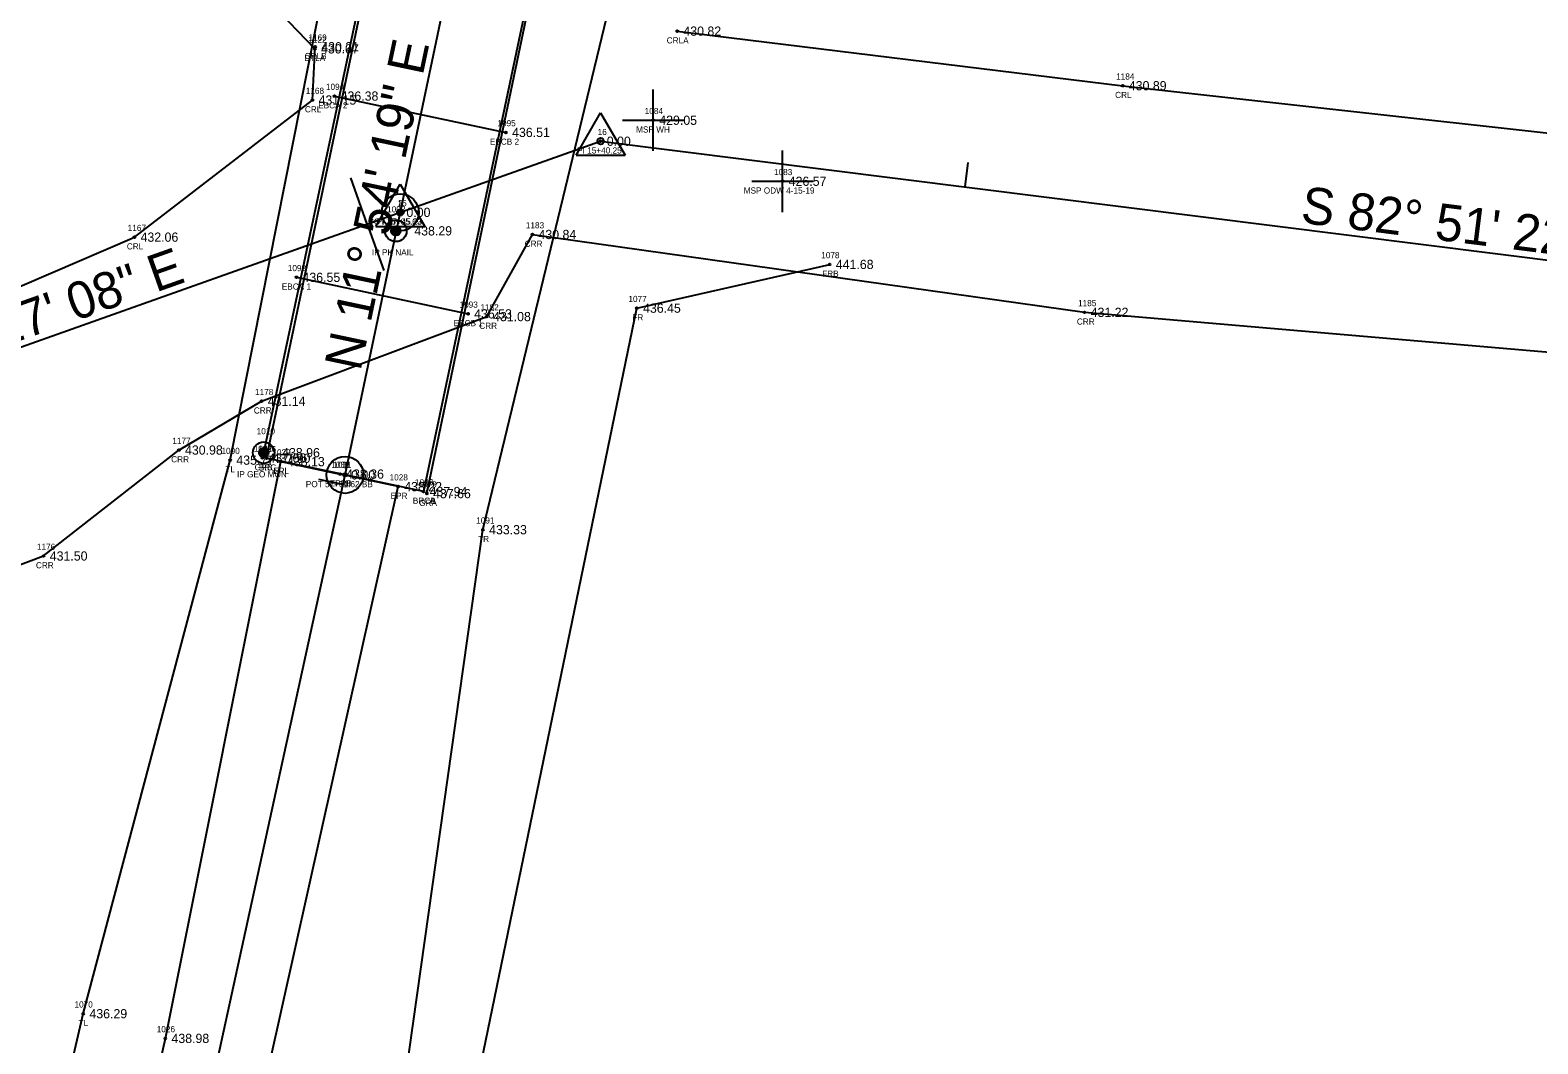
# Model space of a CAD drawing. Extents: x 1754677 to 1756729, y 972996 to 978369.
# Drawn here: x 1756142.4 to 1756387.5, y 976466.6 to 976631.3 of the extents above; entities that cross this region are included whole.
import ezdxf

# ---------------------------------------------------------------- set-up
doc = ezdxf.new("R2010")
doc.units = 0
for name, color, linetype in [('RD_EX_Bridge', 7, 'Continuous'), ('RD_EX_Bridge_txCode', 7, 'Continuous'), ('RD_EX_DV_Prop_txCode', 7, 'Continuous'), ('RD_EX_DV_PropPin', 7, 'Continuous'), ('RD_EX_Fence_Other', 7, 'Continuous'), ('RD_EX_Fence_Other_txCode', 7, 'Continuous'), ('RD_EX_GuardRail', 7, 'Continuous'), ('RD_EX_GuardRail_txCode', 7, 'Continuous'), ('RD_EX_H2O', 7, 'Continuous'), ('RD_EX_H2O_txCode', 7, 'Continuous'), ('RD_EX_Road', 7, 'Continuous'), ('RD_EX_Road_txCode', 7, 'Continuous'), ('RD_EX_TX_Bridge_ELEV', 7, 'Continuous'), ('RD_EX_TX_DV_Prop_ELEV', 7, 'Continuous'), ('RD_EX_TX_Fence_Other_ELEV', 7, 'Continuous'), ('RD_EX_TX_GuardRail_ELEV', 7, 'Continuous'), ('RD_EX_TX_H2O_ELEV', 7, 'Continuous'), ('RD_EX_TX_Misc_ELEV', 7, 'Continuous'), ('RD_EX_TX_Road_ELEV', 7, 'Continuous'), ('RD_EX_TX_VEG_ELEV', 7, 'Continuous'), ('RD_EX_VEG', 7, 'Continuous'), ('RD_EX_VEG_txCode', 7, 'Continuous'), ('RD_HC_Cl', 7, 'Continuous'), ('RD_HC_Data', 7, 'Continuous'), ('RD_HC_Data_Tic', 7, 'Continuous'), ('RD_HC_Survey_ELEV', 7, 'Continuous'), ('RD_HC_txCode', 7, 'Continuous'), ('RD_SMD_Locator', 7, 'Continuous')]:
    doc.layers.add(name, color=color, linetype=linetype)

msp = doc.modelspace()

# ---------------------------------------------------------------- linework, layer by layer
at = {"layer": 'RD_EX_Bridge'}
for p, q in [((1756191.87, 976620.6), (1756219.75, 976614.69)), ((1756185.67, 976591.14), (1756213.58, 976585.2))]:
    msp.add_line(p, q, dxfattribs=at)
msp.add_lwpolyline([(1756206.34, 976556.33), (1756180.82, 976561.73), (1756199.29, 976649.61), (1756224.9, 976644.09), (1756206.34, 976556.33)], dxfattribs=at)
at = {"layer": 'RD_EX_DV_PropPin'}
for p, q in [((1756201.11, 976598.49), (1756201.11, 976598.88)), ((1756201.15, 976598.39), (1756201.15, 976598.99)), ((1756201.18, 976598.32), (1756201.18, 976599.06)), ((1756201.22, 976598.26), (1756201.22, 976599.11)), ((1756201.25, 976598.21), (1756201.25, 976599.16)), ((1756201.29, 976598.17), (1756201.29, 976599.2)), ((1756201.32, 976598.14), (1756201.32, 976599.24)), ((1756201.36, 976598.11), (1756201.36, 976599.27)), ((1756201.39, 976598.08), (1756201.39, 976599.3)), ((1756201.43, 976598.05), (1756201.43, 976599.32)), ((1756201.46, 976598.03), (1756201.46, 976599.34)), ((1756201.5, 976598.01), (1756201.5, 976599.36)), ((1756201.53, 976598), (1756201.53, 976599.38)), ((1756201.57, 976597.98), (1756201.57, 976599.4)), ((1756201.6, 976597.97), (1756201.6, 976599.41)), ((1756201.64, 976597.96), (1756201.64, 976599.42)), ((1756201.67, 976597.95), (1756201.67, 976599.43)), ((1756201.71, 976597.94), (1756201.71, 976599.44)), ((1756201.74, 976597.93), (1756201.74, 976599.44)), ((1756201.78, 976597.93), (1756201.78, 976599.45)), ((1756201.81, 976597.93), (1756201.81, 976599.45)), ((1756201.85, 976597.93), (1756201.85, 976599.45)), ((1756201.88, 976597.93), (1756201.88, 976599.45)), ((1756201.92, 976597.93), (1756201.92, 976599.45)), ((1756201.95, 976597.93), (1756201.95, 976599.44)), ((1756201.99, 976597.94), (1756201.99, 976599.44)), ((1756202.02, 976597.95), (1756202.02, 976599.43)), ((1756202.06, 976597.96), (1756202.06, 976599.42)), ((1756202.09, 976597.97), (1756202.09, 976599.41)), ((1756202.13, 976597.98), (1756202.13, 976599.4)), ((1756202.16, 976598), (1756202.16, 976599.38)), ((1756202.2, 976598.01), (1756202.2, 976599.36)), ((1756202.23, 976598.03), (1756202.23, 976599.34)), ((1756202.27, 976598.05), (1756202.27, 976599.32)), ((1756202.3, 976598.08), (1756202.3, 976599.3)), ((1756202.34, 976598.11), (1756202.34, 976599.27)), ((1756202.37, 976598.14), (1756202.37, 976599.24)), ((1756202.41, 976598.17), (1756202.41, 976599.2)), ((1756202.44, 976598.21), (1756202.44, 976599.16)), ((1756202.48, 976598.26), (1756202.48, 976599.11)), ((1756202.51, 976598.32), (1756202.51, 976599.06)), ((1756202.55, 976598.39), (1756202.55, 976598.99)), ((1756202.58, 976598.49), (1756202.58, 976598.88)), ((1756179.63, 976562.44), (1756179.63, 976562.84)), ((1756179.66, 976562.34), (1756179.66, 976562.94)), ((1756179.7, 976562.27), (1756179.7, 976563.01)), ((1756179.73, 976562.21), (1756179.73, 976563.07)), ((1756179.77, 976562.17), (1756179.77, 976563.11)), ((1756179.8, 976562.12), (1756179.8, 976563.15)), ((1756179.84, 976562.09), (1756179.84, 976563.19)), ((1756179.87, 976562.06), (1756179.87, 976563.22)), ((1756179.91, 976562.03), (1756179.91, 976563.25)), ((1756179.94, 976562.01), (1756179.94, 976563.27)), ((1756179.98, 976561.98), (1756179.98, 976563.3)), ((1756180.01, 976561.96), (1756180.01, 976563.32)), ((1756180.05, 976561.95), (1756180.05, 976563.33)), ((1756180.08, 976561.93), (1756180.08, 976563.35)), ((1756180.12, 976561.92), (1756180.12, 976563.36)), ((1756180.15, 976561.91), (1756180.15, 976563.37)), ((1756180.19, 976561.9), (1756180.19, 976563.38)), ((1756180.22, 976561.89), (1756180.22, 976563.39)), ((1756180.26, 976561.89), (1756180.26, 976563.39)), ((1756180.29, 976561.88), (1756180.29, 976563.4)), ((1756180.33, 976561.88), (1756180.33, 976563.4)), ((1756180.36, 976561.88), (1756180.36, 976563.4)), ((1756180.4, 976561.88), (1756180.4, 976563.4)), ((1756180.43, 976561.88), (1756180.43, 976563.4)), ((1756180.47, 976561.89), (1756180.47, 976563.39)), ((1756180.5, 976561.89), (1756180.5, 976563.39)), ((1756180.54, 976561.9), (1756180.54, 976563.38)), ((1756180.57, 976561.91), (1756180.57, 976563.37)), ((1756180.61, 976561.92), (1756180.61, 976563.36)), ((1756180.64, 976561.93), (1756180.64, 976563.35)), ((1756180.68, 976561.95), (1756180.68, 976563.33)), ((1756180.71, 976561.96), (1756180.71, 976563.32)), ((1756180.75, 976561.98), (1756180.75, 976563.3)), ((1756180.78, 976562.01), (1756180.78, 976563.27)), ((1756180.82, 976562.03), (1756180.82, 976563.25)), ((1756180.85, 976562.06), (1756180.85, 976563.22)), ((1756180.89, 976562.09), (1756180.89, 976563.19)), ((1756180.92, 976562.12), (1756180.92, 976563.15)), ((1756180.96, 976562.17), (1756180.96, 976563.11)), ((1756180.99, 976562.21), (1756180.99, 976563.07)), ((1756181.03, 976562.27), (1756181.03, 976563.01)), ((1756181.06, 976562.34), (1756181.06, 976562.94)), ((1756181.1, 976562.44), (1756181.1, 976562.84))]:
    msp.add_line(p, q, dxfattribs=at)
for centre, radius in [((1756201.85, 976598.69), 1.75), ((1756201.85, 976598.69), 0.761), ((1756180.36, 976562.64), 1.75), ((1756180.36, 976562.64), 0.761)]:
    msp.add_circle(centre, radius, dxfattribs=at)
at = {"layer": 'RD_EX_Fence_Other'}
msp.add_lwpolyline([(1756175.64, 976319.57), (1756180.92, 976337.06), (1756180.92, 976337.06), (1756189.99, 976367.43), (1756214.31, 976456.61), (1756241.04, 976586.13), (1756272.38, 976593.24)], dxfattribs=at)
at = {"layer": 'RD_EX_GuardRail'}
for p, q in [((1756198.88, 976649.87), (1756180.14, 976561.78)), ((1756206.9, 976555.99), (1756225.37, 976644.33))]:
    msp.add_line(p, q, dxfattribs=at)
at = {"layer": 'RD_EX_H2O'}
for p, q in [((1756243.68, 976611.67), (1756243.68, 976621.67)), ((1756238.68, 976616.67), (1756248.68, 976616.67)), ((1756264.72, 976601.75), (1756264.72, 976611.75)), ((1756259.72, 976606.75), (1756269.72, 976606.75))]:
    msp.add_line(p, q, dxfattribs=at)
for points in [[(1756188.69, 976628.27), (1756159.54, 976658.6), (1756134.34, 976641.66), (1756096.42, 976639.72), (1756159.17, 976666.78), (1756147.63, 976691.44)], [(1756247.6, 976631.15), (1756320.02, 976622.28), (1756426.93, 976610.4), (1756522.42, 976596.33), (1756612.51, 976536.45), (1756713.08, 976499.13)], [(1755737.32, 976440.59), (1755791.96, 976465.24), (1755883.28, 976455.13), (1755971.27, 976482.19), (1756023.59, 976552.72), (1756109.16, 976576.08), (1756159.34, 976597.67), (1756188.28, 976619.95), (1756188.72, 976628.61)], [(1755755.31, 976405), (1755806.36, 976424.52), (1755883.37, 976426.21), (1755989.26, 976449.51), (1756040.99, 976524.41), (1756109.22, 976532.55), (1756144.58, 976545.85), (1756166.57, 976563.07), (1756180.02, 976571), (1756216.66, 976584.76), (1756224.04, 976598.1), (1756313.82, 976585.45), (1756418.42, 976576.49), (1756511.71, 976558.86), (1756604.42, 976511.73), (1756702.67, 976481.09)]]:
    msp.add_lwpolyline(points, dxfattribs=at)
for centre in [(1756243.68, 976616.67), (1756264.72, 976606.75)]:
    msp.add_circle(centre, 0.15, dxfattribs=at)
at = {"layer": 'RD_EX_Road'}
for points in [[(1756035.19, 975875.88), (1756056.24, 975973.07), (1756076.6, 976069.51), (1756097.1, 976167.18), (1756119.62, 976269.35), (1756142.72, 976371.31), (1756164.37, 976467.45), (1756183.15, 976561.19), (1756192.77, 976559.17)], [(1756056.66, 975870.37), (1756077.66, 975967.46), (1756097.63, 976065.09), (1756118.05, 976161.7), (1756139.04, 976265.41), (1756152.93, 976328.23), (1756161.13, 976367.36), (1756181.28, 976463.3), (1756202.22, 976557.13), (1756192.77, 976559.17)]]:
    msp.add_lwpolyline(points, dxfattribs=at)
at = {"layer": 'RD_EX_VEG'}
for points in [[(1756025.5, 975878.35), (1756043.1, 975975.5), (1756066.95, 976073.5), (1756085.77, 976169.9), (1756104.86, 976272.18), (1756128.74, 976375.38), (1756151.03, 976471.46), (1756174.91, 976561.43), (1756192.74, 976651.33), (1756213.53, 976750.19), (1756228.91, 976849.58), (1756256.36, 976947.04), (1756269.46, 977047.7), (1756289.25, 977149.19), (1756313.02, 977250.02), (1756334.73, 977344.93)], [(1756202.82, 976314.6), (1756169.5, 976324.56), (1756203.44, 976461.03), (1756216.01, 976550.12), (1756241.68, 976656.38), (1756259.33, 976737.2), (1756283.06, 976837.69), (1756302.86, 976939.77), (1756320.41, 977034.15), (1756341.85, 977139.2), (1756364.03, 977240.9), (1756380.52, 977337.93)]]:
    msp.add_lwpolyline(points, dxfattribs=at)
at = {"layer": 'RD_HC_Cl'}
for p, q in [((1756193.58, 976559.03), (1756212.09, 976646.85)), ((1756051.41, 976548.03), (1756235.14, 976613.26)), ((1756235.14, 976613.26), (1756516.31, 976578.02)), ((1756107.58, 976164.44), (1756193.58, 976559.03))]:
    msp.add_line(p, q, dxfattribs=at)
at = {"layer": 'RD_HC_Data'}
for p, q in [((1756231.16, 976610.97), (1756235.14, 976617.85)), ((1756235.14, 976617.85), (1756239.11, 976610.97)), ((1756231.16, 976610.97), (1756239.11, 976610.97)), ((1756198.6, 976599.41), (1756202.57, 976606.29)), ((1756202.57, 976606.29), (1756206.54, 976599.41)), ((1756198.6, 976599.41), (1756206.54, 976599.41))]:
    msp.add_line(p, q, dxfattribs=at)
for centre, radius in [((1756235.14, 976613.26), 0.529), ((1756202.57, 976601.7), 3), ((1756202.57, 976601.7), 0.529), ((1756202.57, 976601.7), 0.282), ((1756193.58, 976559.03), 3), ((1756193.58, 976559.03), 0.282)]:
    msp.add_circle(centre, radius, dxfattribs=at)
at = {"layer": 'RD_HC_Data_Tic'}
for p, q in [((1756294.42, 976605.83), (1756294.92, 976609.8)), ((1756197.21, 976599.8), (1756194.53, 976607.33)), ((1756197.21, 976599.8), (1756199.88, 976592.26)), ((1756193.23, 976557.45), (1756189.32, 976558.3))]:
    msp.add_line(p, q, dxfattribs=at)
at = {"layer": 'RD_SMD_Locator'}
for centre in [(1756247.6, 976631.15), (1756188.69, 976628.27), (1756188.72, 976628.61), (1756320.02, 976622.28), (1756188.28, 976619.95), (1756191.87, 976620.6), (1756219.75, 976614.69), (1756235.14, 976613.26), (1756202.57, 976601.7), (1756202.57, 976601.7), (1756159.34, 976597.67), (1756201.85, 976598.69), (1756224.04, 976598.1), (1756272.38, 976593.24), (1756185.67, 976591.14), (1756213.58, 976585.2), (1756216.66, 976584.76), (1756241.04, 976586.13), (1756313.82, 976585.45), (1756180.02, 976571), (1756166.57, 976563.07), (1756180.36, 976562.64), (1756174.91, 976561.43), (1756180.14, 976561.78), (1756180.82, 976561.73), (1756183.15, 976561.19), (1756192.77, 976559.17), (1756192.77, 976559.17), (1756193.58, 976559.03), (1756202.22, 976557.13), (1756206.34, 976556.33), (1756206.34, 976556.33), (1756206.9, 976555.99), (1756216.01, 976550.12), (1756144.58, 976545.85), (1756151.03, 976471.46), (1756164.37, 976467.45)]:
    msp.add_circle(centre, 0.15, dxfattribs=at)

# ---------------------------------------------------------------- texts
at = {"layer": 'RD_EX_Bridge_txCode'}
for s, p in [('1094', (1756190.48, 976621.6)), ('EBCA 2', (1756189.22, 976618.6)), ('1095', (1756218.36, 976615.69)), ('EBCB 2', (1756217.13, 976612.69)), ('1092', (1756184.28, 976592.14)), ('EBCA 1', (1756183.3, 976589.14)), ('1093', (1756212.2, 976586.2)), ('EBCB 1', (1756211.24, 976583.2)), ('1086', (1756179.41, 976562.73)), ('BRC', (1756179.57, 976559.73)), ('1085', (1756204.95, 976557.33)), ('1089', (1756204.95, 976557.33)), ('BRCA', (1756204.6, 976554.33)), ('BRCB', (1756204.61, 976554.33))]:
    msp.add_text(s, height=1, dxfattribs=at).set_placement(p)
at = {"layer": 'RD_EX_DV_Prop_txCode'}
for s, p in [('1002', (1756200.42, 976601.69)), ('IP PK NAIL', (1756197.96, 976594.69)), ('1010', (1756179.22, 976565.64)), ('IP GEO MON', (1756176.02, 976558.64))]:
    msp.add_text(s, height=1, dxfattribs=at).set_placement(p)
at = {"layer": 'RD_EX_Fence_Other_txCode'}
for s, p in [('1078', (1756271, 976594.24)), ('FRB', (1756271.16, 976591.24)), ('1077', (1756239.66, 976587.13)), ('FR', (1756240.29, 976584.13))]:
    msp.add_text(s, height=1, dxfattribs=at).set_placement(p)
at = {"layer": 'RD_EX_GuardRail_txCode'}
for s, p in [('1082', (1756178.76, 976562.78)), ('GRB', (1756178.89, 976559.78)), ('1079', (1756205.52, 976556.99)), ('GRA', (1756205.64, 976553.99))]:
    msp.add_text(s, height=1, dxfattribs=at).set_placement(p)
at = {"layer": 'RD_EX_H2O_txCode'}
for s, p in [('1122', (1756187.62, 976629.27)), ('1169', (1756187.64, 976629.61)), ('CRLA', (1756245.88, 976629.15)), ('DTLA', (1756186.95, 976626.27)), ('CRLB', (1756187.02, 976626.61)), ('1184', (1756318.95, 976623.28)), ('1168', (1756187.2, 976620.95)), ('CRL', (1756318.79, 976620.28)), ('CRL', (1756187.06, 976617.95)), ('1084', (1756242.3, 976617.67)), ('MSP WH', (1756240.91, 976614.67)), ('1083', (1756263.33, 976607.75)), ('MSP ODW 4-15-19', (1756258.4, 976604.75)), ('1167', (1756158.25, 976598.67)), ('1183', (1756222.98, 976599.1)), ('CRL', (1756158.11, 976595.67)), ('CRR', (1756222.79, 976596.1)), ('1182', (1756215.6, 976585.76)), ('1185', (1756312.76, 976586.45)), ('CRR', (1756312.57, 976583.45)), ('CRR', (1756215.41, 976582.76)), ('1178', (1756178.95, 976572)), ('CRR', (1756178.76, 976569)), ('1177', (1756165.51, 976564.07)), ('CRR', (1756165.32, 976561.07)), ('1176', (1756143.49, 976546.85)), ('CRR', (1756143.33, 976543.85))]:
    msp.add_text(s, height=1, dxfattribs=at).set_placement(p)
at = {"layer": 'RD_EX_Road_txCode'}
for s, p in [('1029', (1756181.77, 976562.19)), ('EPL', (1756181.95, 976559.19)), ('1030', (1756191.34, 976560.17)), ('1031', (1756191.67, 976560.17)), ('EPRB', (1756191.07, 976557.17)), ('EPLB', (1756191.09, 976557.17)), ('1028', (1756200.83, 976558.13)), ('EPR', (1756200.99, 976555.13)), ('1026', (1756162.97, 976468.45))]:
    msp.add_text(s, height=1, dxfattribs=at).set_placement(p)
at = {"layer": 'RD_EX_TX_Bridge_ELEV'}
for s, p in [('436.38', (1756192.87, 976619.85)), ('436.51', (1756220.75, 976613.94)), ('436.55', (1756186.67, 976590.39)), ('436.53', (1756214.58, 976584.45)), ('437.90', (1756181.82, 976560.98)), ('437.94', (1756207.34, 976555.58)), ('437.94', (1756207.34, 976555.58))]:
    msp.add_text(s, height=1.5, dxfattribs=at).set_placement(p)
at = {"layer": 'RD_EX_TX_DV_Prop_ELEV'}
for s, p in [('438.29', (1756204.85, 976597.94)), ('438.96', (1756183.36, 976561.89))]:
    msp.add_text(s, height=1.5, dxfattribs=at).set_placement(p)
at = {"layer": 'RD_EX_TX_Fence_Other_ELEV'}
for s, p in [('441.68', (1756273.38, 976592.49)), ('436.45', (1756242.04, 976585.38))]:
    msp.add_text(s, height=1.5, dxfattribs=at).set_placement(p)
at = {"layer": 'RD_EX_TX_GuardRail_ELEV'}
for p in [(1756181.14, 976561.03), (1756207.9, 976555.24)]:
    msp.add_text('437.66', height=1.5, dxfattribs=at).set_placement(p)
at = {"layer": 'RD_EX_TX_H2O_ELEV'}
for s, p in [('430.82', (1756248.6, 976630.4)), ('430.07', (1756189.69, 976627.52)), ('430.21', (1756189.72, 976627.86)), ('430.89', (1756321.02, 976621.53)), ('431.15', (1756189.28, 976619.2)), ('432.06', (1756160.34, 976596.92)), ('430.84', (1756225.04, 976597.35)), ('431.08', (1756217.66, 976584.01)), ('431.22', (1756314.82, 976584.7)), ('431.14', (1756181.02, 976570.25)), ('430.98', (1756167.57, 976562.32)), ('431.50', (1756145.58, 976545.1))]:
    msp.add_text(s, height=1.5, dxfattribs=at).set_placement(p)
at = {"layer": 'RD_EX_TX_Misc_ELEV'}
for s, p in [('429.05', (1756244.68, 976615.92)), ('426.57', (1756265.72, 976606))]:
    msp.add_text(s, height=1.5, dxfattribs=at).set_placement(p)
at = {"layer": 'RD_EX_TX_Road_ELEV'}
for s, p in [('438.13', (1756184.15, 976560.44)), ('438.36', (1756193.77, 976558.42)), ('438.36', (1756193.77, 976558.42)), ('438.22', (1756203.22, 976556.38)), ('438.98', (1756165.37, 976466.7))]:
    msp.add_text(s, height=1.5, dxfattribs=at).set_placement(p)
at = {"layer": 'RD_EX_TX_VEG_ELEV'}
for s, p in [('435.77', (1756175.91, 976560.68)), ('433.33', (1756217.01, 976549.37)), ('436.29', (1756152.03, 976470.71))]:
    msp.add_text(s, height=1.5, dxfattribs=at).set_placement(p)
at = {"layer": 'RD_EX_VEG_txCode'}
for s, p in [('1090', (1756173.49, 976562.43)), ('TL', (1756174.14, 976559.43)), ('1091', (1756214.91, 976551.12)), ('TR', (1756215.22, 976548.12)), ('1070', (1756149.6, 976472.46)), ('TL', (1756150.26, 976469.46))]:
    msp.add_text(s, height=1, dxfattribs=at).set_placement(p)
at = {"layer": 'RD_HC_Data'}
for s, rotation, p in [('N 11%%d 54\' 19" E', 78.0946, (1756196.08, 976575.77)), ('S 82%%d 51\' 22" E', 352.856, (1756348.82, 976600.02)), ('N 70%%d 27\' 08" E', 19.5477, (1756116.57, 976572.23))]:
    msp.add_text(s, height=6, rotation=rotation, dxfattribs=at).set_placement(p)
at = {"layer": 'RD_HC_Survey_ELEV'}
for p in [(1756236.14, 976612.51), (1756203.57, 976600.95), (1756203.57, 976600.95), (1756194.58, 976558.28)]:
    msp.add_text('0.00', height=1.5, dxfattribs=at).set_placement(p)
at = {"layer": 'RD_HC_txCode'}
for s, p in [('16', (1756234.66, 976614.26)), ('PI 15+40.25', (1756231.32, 976611.26)), ('15', (1756202.12, 976602.7)), ('8', (1756202.29, 976602.7)), ('POT 57+45.23', (1756197.38, 976599.7)), ('PI 15+05.69', (1756198.73, 976599.7)), ('7', (1756193.29, 976560.03)), ('POT 57+01.62 BB', (1756187.21, 976557.03))]:
    msp.add_text(s, height=1, dxfattribs=at).set_placement(p)

doc.saveas('drawing.dxf')
